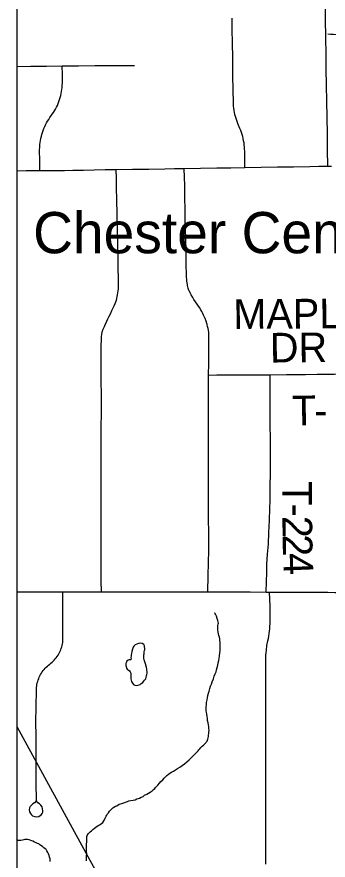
# Model space of a CAD drawing. Extents: x 103424 to 286016, y 38711 to 110967.
# Drawn here: x 103424 to 106590, y 76283 to 84863 of the extents above; entities that cross this region are included whole.
import ezdxf

# ---------------------------------------------------------------- set-up
doc = ezdxf.new("R2010")
doc.units = 0
for name, color, linetype in [('GM_X_Corporation', 7, 'Continuous'), ('GM_X_Minor_Lake', 7, 'Continuous'), ('GM_X_Minor_River', 7, 'Continuous'), ('GM_X_Rail_Line', 7, 'Continuous'), ('GM_X_Township_Road', 7, 'Continuous'), ('GM_X_Township_Road_Text', 7, 'Continuous'), ('GM_X_Unincorporated_Text', 7, 'Continuous'), ('GM_X_US_Route', 7, 'Continuous')]:
    doc.layers.add(name, color=color, linetype=linetype)

msp = doc.modelspace()

# ---------------------------------------------------------------- linework, layer by layer
at = {"layer": 'GM_X_Corporation'}
msp.add_lwpolyline([(103423.7, 96534.8), (103423.7, 38711.2), (175679.7, 38711.2), (175679.7, 110967.2), (119699, 110967.2), (119716.9, 106542.5), (119719.8, 106322.8), (119720.8, 106006.3), (119709.7, 99445.7), (119706.4, 99064.2), (119663.9, 96690), (117026.4, 96688.2), (115542.1, 96665), (105081.7, 96574.5)], close=True, dxfattribs=at)
msp.add_lwpolyline([(103423.7, 96534.8), (103423.7, 70904.9), (107977, 70917.3), (117928.9, 70934.4), (117946.9, 70934.9), (119688.2, 70990.2), (119635, 74016.7), (119631.7, 75117.1), (119628.6, 75451.2), (119621.3, 75805.1), (119622.8, 76073.8), (119627.2, 76341.1), (119628.6, 76885.8), (119631.6, 77245.6), (119644.2, 78899.8), (119644.5, 79431.3), (119642.9, 80216.4), (119641.6, 80653.5), (119641.6, 81200.9), (119640.3, 81697.7), (119639, 82590.1), (119639, 83128.3), (119639, 84504.6), (119641.6, 85722.3)], dxfattribs=at)
at = {"layer": 'GM_X_Minor_Lake'}
for points in [[(104660.3, 78487.2), (104626.1, 78474.7), (104612.2, 78458.4), (104606.2, 78448.3), (104600.4, 78430), (104594.6, 78405.7), (104588.8, 78383.4), (104586.9, 78371.3), (104585.1, 78357.2), (104583.2, 78345), (104587.4, 78330.9), (104581.5, 78320.8), (104567.3, 78320.6), (104557.3, 78318.5), (104543.3, 78306.2), (104539.3, 78296.1), (104533.4, 78281.9), (104533.6, 78271.8), (104531.7, 78261.7), (104533.8, 78251.6), (104538, 78237.5), (104544.2, 78225.5), (104556.4, 78217.5), (104568.6, 78209.5), (104576.8, 78199.5), (104583, 78185.4), (104583.2, 78175.3), (104581.4, 78155.1), (104581.5, 78143), (104583.7, 78128.9), (104585.9, 78112.7), (104590.1, 78100.7), (104598.4, 78082.6), (104612.7, 78066.6), (104624.8, 78062.6), (104639, 78060.8), (104655.1, 78062.9), (104667.2, 78067.1), (104677.3, 78071.2), (104689.3, 78079.4), (104703.3, 78091.7), (104713.3, 78099.9), (104723.2, 78112.1), (104735.2, 78128.4), (104739.1, 78140.5), (104742.9, 78160.8), (104746.8, 78170.9), (104748.7, 78185.1), (104748.5, 78199.2), (104746.3, 78217.4), (104744.1, 78227.4), (104741.9, 78243.6), (104731.4, 78279.8), (104729.3, 78289.9), (104718.7, 78320.9)], [(104718.7, 78320.9), (104716.6, 78334.2), (104714.5, 78346.3), (104714.4, 78356.4), (104716.2, 78370.6), (104718.1, 78382.7), (104718, 78392.8), (104719.9, 78402.9), (104721.7, 78415.1), (104725.6, 78427.2), (104725.5, 78437.3), (104723.3, 78451.5), (104721.2, 78461.5), (104715, 78475.6), (104698.7, 78485.6), (104684.5, 78489.4), (104668.4, 78487.3), (104660.3, 78487.2)]]:
    msp.add_lwpolyline(points, dxfattribs=at)
at = {"layer": 'GM_X_Minor_River'}
for points in [[(105058.9, 77214.6), (105082.9, 77228.9), (105105, 77245.3), (105129, 77263.7), (105153, 77282.2), (105175, 77304.6), (105194.9, 77325), (105214.9, 77341.4), (105230.9, 77357.7), (105246.9, 77374), (105256.8, 77384.2), (105266.8, 77394.4), (105274.8, 77404.6), (105284.8, 77414.8), (105294.7, 77427), (105308.7, 77441.3), (105320.7, 77453.5), (105332.7, 77461.7), (105358.6, 77492.3), (105362.5, 77504.4), (105366.4, 77514.6), (105370.3, 77526.7), (105372.2, 77540.9), (105374, 77557.1), (105375.9, 77571.2), (105377.7, 77583.3), (105379.5, 77601.6), (105377.3, 77621.7), (105375.1, 77637.9), (105372.8, 77658), (105368.6, 77678.2), (105364.2, 77702.4), (105361.9, 77724.6), (105357.7, 77744.7), (105355.4, 77766.9), (105351.1, 77787.1), (105348.9, 77803.2), (105348.7, 77819.4), (105348.5, 77841.6), (105352.3, 77863.9), (105354, 77886.1), (105357.7, 77912.4), (105361.5, 77934.7), (105365.3, 77956.9), (105371.1, 77981.2), (105378.9, 78003.5), (105384.7, 78027.8), (105392.5, 78052.1), (105402.3, 78072.4), (105410.1, 78096.7), (105423.9, 78127.2), (105431.7, 78153.5), (105441.5, 78177.9), (105449.3, 78200.2), (105455.2, 78220.4), (105461, 78242.7), (105466.7, 78267), (105472.5, 78289.3), (105476.3, 78313.5), (105480.1, 78335.8), (105483.8, 78360.1), (105487.5, 78390.4), (105491.3, 78414.7), (105491, 78436.9), (105492.8, 78459.1), (105492.5, 78483.4), (105487.9, 78533.8), (105483.6, 78550), (105479.4, 78568.1), (105475.2, 78584.2), (105470.9, 78602.3), (105468.6, 78628.6), (105468.3, 78650.8), (105468.1, 78669), (105470, 78683.1), (105473.9, 78695.3), (105471.7, 78707.4), (105467.5, 78721.5), (105461.2, 78739.6), (105454.9, 78765.8), (105444.6, 78783.9), (105436.4, 78793.9), (105434.3, 78795.9)], [(104132.6, 76276.1), (104132, 76330.7), (104133.8, 76348.8), (104133.6, 76367), (104131.3, 76387.2), (104133.1, 76405.4), (104132.9, 76423.6), (104132.7, 76445.8), (104134.4, 76470), (104134.1, 76494.3), (104135.9, 76510.5), (104135.8, 76522.6), (104139.7, 76532.7), (104149.6, 76549), (104167.6, 76569.4), (104181.6, 76581.6), (104197.6, 76595.9), (104211.6, 76608.2), (104225.6, 76616.4), (104239.6, 76626.6), (104255.7, 76636.9), (104269.7, 76645.1), (104283.7, 76655.4), (104297.7, 76665.6), (104307.6, 76683.9), (104313.6, 76694), (104321.5, 76710.3), (104331.3, 76730.6), (104337.3, 76740.7), (104345.2, 76755), (104355.2, 76763.1), (104365.1, 76781.4), (104375.1, 76791.6), (104385, 76801.8), (104399, 76814.1), (104411, 76822.3), (104427.1, 76832.5), (104439.2, 76836.7), (104465.2, 76851.1), (104479.3, 76855.3), (104491.4, 76859.4), (104501.5, 76863.6), (104549.7, 76880.2), (104563.8, 76884.4), (104584, 76888.6), (104606.1, 76892.9), (104626.3, 76897.1), (104644.4, 76905.4), (104670.5, 76913.7), (104688.6, 76922), (104706.7, 76930.3), (104722.7, 76942.5), (104744.8, 76954.9), (104762.9, 76963.1), (104780.9, 76973.4), (104798.9, 76987.7), (104814.9, 77002), (104826.9, 77012.3), (104834.9, 77022.4), (104846.8, 77036.7), (104856.8, 77046.9), (104874.7, 77067.3), (104888.7, 77083.6), (104906.7, 77099.9), (104922.6, 77118.3), (104936.6, 77130.5), (104950.6, 77144.8), (104964.6, 77157), (104980.6, 77167.3), (104996.7, 77177.6), (105016.7, 77187.9), (105036.8, 77200.2), (105058.9, 77214.6)], [(103763.1, 76270.4), (103760.8, 76294.6), (103756.5, 76312.8), (103752.3, 76330.9), (103746, 76347), (103737.8, 76361.1), (103729.5, 76377.1), (103721.3, 76389.2), (103711.1, 76397.1), (103696.8, 76409.1), (103684.6, 76421.1), (103666.2, 76433.1), (103656.1, 76439), (103645.9, 76447), (103633.7, 76452.9), (103619.5, 76458.8), (103603.2, 76466.8), (103585, 76474.7), (103564.7, 76482.5), (103548.5, 76488.4), (103532.3, 76492.3), (103518.1, 76494.2), (103504, 76494.1), (103493.9, 76489.9), (103479.8, 76485.7), (103465.7, 76483.6), (103455.6, 76481.4), (103439.5, 76481.3), (103427.3, 76483.2), (103423.7, 76489.5)]]:
    msp.add_lwpolyline(points, dxfattribs=at)
at = {"layer": 'GM_X_Rail_Line'}
msp.add_lwpolyline([(103423.7, 77642.6), (104166, 76280.9), (107163.5, 70870.4), (107374.6, 70584.2), (107548.1, 70377.7), (107675.1, 70305.5), (107983.3, 70249.1), (108679.2, 69977.3), (109351.9, 69695.5), (110309.6, 69221.5), (110614.5, 69082.2), (110922.7, 69062.3), (111038.6, 69148.5), (111217.6, 69480), (111333.6, 69665.7), (111519.1, 69795), (111678.2, 69838), (112046, 69785), (112529.9, 69702.1), (112964, 69695.5)], dxfattribs=at)
at = {"layer": 'GM_X_Township_Road'}
for points in [[(106566, 84636.9), (106565.5, 84663.5), (106562.9, 84828.5), (106561.2, 84927.4), (106559.6, 85026.3), (106558.1, 85043.8), (106555.1, 85061.2), (106551.1, 85078.3), (106544.3, 85099.2), (106535.7, 85119.4), (106527.7, 85135), (106518.6, 85150), (106508.3, 85164.3), (106497.3, 85177.9), (106424.8, 85261.5)], [(105743.7, 83329.7), (105742.5, 83412.3), (105741.3, 83494.9), (105740.6, 83516.5), (105739.3, 83538.1), (105737, 83559.6), (105734, 83581.1), (105730.3, 83602.5), (105725.7, 83623.6), (105720.7, 83644.6), (105714.7, 83665.4), (105708.1, 83686), (105700.8, 83706.4), (105692.8, 83726.4), (105675.2, 83766), (105667.2, 83786.1), (105659.9, 83806.5), (105653.1, 83827), (105647.3, 83847.8), (105642, 83868.8), (105637.5, 83890), (105634, 83911.3), (105631, 83932.8), (105628.7, 83954.3), (105627.2, 83975.9), (105626.5, 83997.5), (105624.5, 84109.9), (105621.8, 84274.9), (105619.2, 84439.9), (105616.5, 84605), (105614.6, 84727.5), (105612.6, 84850)], [(106586.2, 84688.6), (106615.2, 84687), (106642.8, 84685.4), (106725, 84684.6), (106890, 84685.9), (107008.4, 84686.8), (107126.8, 84687.8), (107291.8, 84690.6), (107456.8, 84693.3), (107563.3, 84695.1), (107669.8, 84696.9), (107834.8, 84699), (107937.2, 84700.2), (108039.7, 84701.5), (108158.9, 84700.6), (108278.1, 84699.8)], [(106587, 83343.2), (106584.4, 83508.2), (106581.7, 83673.3), (106579, 83838.3), (106576.3, 84003.3), (106573.6, 84168.4), (106570.9, 84333.4), (106568.2, 84498.4), (106566, 84636.9)], [(103423.7, 84359), (103561.7, 84360.3), (103723.8, 84361.9), (103885.9, 84363.4), (104051, 84364.7), (104216.1, 84366), (104381.1, 84367.3), (104500.7, 84368.3), (104620.2, 84369.3)], [(103657.4, 83298.7), (103656.4, 83400.1), (103655.5, 83501.5), (103656.7, 83543.5), (103658.5, 83564.4), (103660.8, 83585.3), (103664.1, 83606), (103668.1, 83626.6), (103672.9, 83647), (103678.2, 83667.2), (103684.5, 83687.3), (103691.3, 83707.1), (103698.9, 83726.7), (103707.4, 83745.9), (103716.3, 83764.9), (103726.1, 83783.4), (103736.4, 83801.6), (103747.5, 83819.5), (103759.1, 83837), (103783.8, 83870.9), (103795.3, 83888.3), (103806.4, 83906.1), (103816.8, 83924.4), (103826.6, 83943), (103835.7, 83961.9), (103844, 83981.2), (103851.5, 84000.7), (103858.6, 84020.5), (103864.6, 84040.5), (103870.2, 84060.8), (103874.7, 84081.3), (103878.8, 84101.8), (103882.1, 84122.5), (103884.6, 84143.3), (103886.1, 84164.3), (103886.8, 84186.8), (103886.4, 84275.1), (103885.9, 84363.4)], [(104434.8, 83309), (104599.8, 83311.6), (104764.9, 83314.1), (104929.9, 83316.7), (105028.3, 83318.2), (105126.7, 83319.7), (105291.7, 83322.4), (105456.7, 83325.1), (105600.3, 83327.4), (105743.7, 83329.7), (105908.8, 83332.4), (106073.8, 83335), (106238.8, 83337.7), (106403.9, 83340.3), (106495.5, 83341.8), (106587, 83343.2), (106625.5, 83343.8)], [(105367.5, 79012.1), (105370.5, 79177.2), (105372.8, 79306.8), (105375.1, 79436.4), (105374.7, 79601.5), (105374.3, 79766.5), (105373.8, 79931.6), (105373.4, 80096.7), (105373, 80225.5), (105372.7, 80354.2), (105373.9, 81217.4), (105374.8, 81340.2), (105375.7, 81463.1), (105376.3, 81603.3), (105375, 81653.3), (105368.6, 81692.3), (105364.1, 81710.8), (105359.1, 81731.9), (105355.5, 81743.9), (105348, 81765.4), (105338.1, 81793.5), (105331.3, 81806.9), (105322.7, 81828.8), (105315.2, 81843.8), (105303.9, 81865.5), (105294.6, 81881.1), (105280.3, 81905.8), (105240.7, 81964), (105225, 81987.6), (105213.3, 82006.2), (105197, 82034.2), (105186.5, 82055.1), (105179.1, 82070.7), (105173.6, 82079.1), (105166.6, 82102.6), (105160.3, 82128.9), (105157.6, 82139.6), (105155.3, 82154.9), (105152.6, 82171.7), (105151, 82188.3), (105150.1, 82219.7), (105147, 82363.3), (105144.7, 82481.3), (105142.4, 82599.3), (105139.5, 82705.6), (105136.7, 82811.8), (105134.9, 82912.6), (105133.1, 83013.3), (105130.6, 83147.4), (105128.6, 83228.3), (105126.7, 83319.7)], [(103423.7, 83297.2), (103428.1, 83297.3), (103518.8, 83297.8), (103657.4, 83298.7), (103822.5, 83300.2), (103907.7, 83301), (103993, 83301.8), (104101.7, 83304.3), (104210.5, 83306.9), (104322.7, 83308), (104434.8, 83309)], [(104282.9, 79012.5), (104281.8, 79123.6), (104281.1, 79270.7), (104280.4, 79417.8), (104280.8, 80349.4), (104281.7, 80514.4), (104282.6, 80677.3), (104283.5, 80840.1), (104282.8, 81005.2), (104282, 81170.2), (104281.2, 81335.3), (104280.8, 81419.2), (104280.4, 81503.2), (104283.5, 81592), (104285.1, 81612.4), (104287.3, 81628.1), (104291.7, 81656.5), (104300.1, 81683.5), (104313.8, 81713.4), (104321.6, 81730.6), (104337.6, 81765), (104349.9, 81789.3), (104359.8, 81809), (104377.9, 81846.8), (104390.6, 81873.3), (104403, 81900.6), (104412.9, 81921.7), (104423, 81945.5), (104429.2, 81962.1), (104435.6, 81981.7), (104440.1, 81997.7), (104445.4, 82017), (104448.8, 82036), (104452.2, 82054.8), (104455, 82073.6), (104456.7, 82090.7), (104458, 82112.5), (104458.6, 82129.3), (104456.7, 82205.1), (104454.6, 82302.4), (104452.5, 82399.7), (104450, 82540.4), (104447.4, 82681.2), (104443.9, 82846.2), (104440.3, 83011.3), (104438.1, 83114.5), (104435.9, 83217.7), (104434.8, 83309)], [(105373.9, 81217.4), (105459.2, 81219.6), (105624.3, 81220.1), (105846.2, 81220.8), (105999.7, 81221.3), (106164.7, 81223.1), (106262.9, 81224.2), (106361, 81225.2), (106479.2, 81226.5), (106597.4, 81227.8), (106650.8, 81227.5), (106783.9, 81229.2), (106916.9, 81230.9), (107018.7, 81232.2), (107120.5, 81233.5)], [(105958.7, 79010.8), (105961.4, 79117.1), (105964.6, 79204.9), (105967.7, 79292.6), (105974.5, 79394.4), (105981.4, 79496.1), (105987.8, 79616.8), (105992.5, 79737.9), (105997.2, 79858.9), (105998.7, 79943.3), (105999.5, 80093), (106002.5, 80213), (106001, 81067.3), (105999.7, 81221.3)], [(103619.6, 76886), (103603.9, 76866.5), (103587.5, 76856.8), (103571, 76841.9), (103559.8, 76829.9), (103553.8, 76813.4), (103549.3, 76793.2), (103552.3, 76775.3), (103561.3, 76758.1), (103571.7, 76743.9), (103583, 76734.9), (103606.1, 76726), (103622.6, 76723.7), (103647.3, 76728.2), (103661.5, 76737.9), (103673.5, 76747.6), (103682.4, 76758.1), (103687.6, 76770.1), (103689.2, 76784.3), (103682.4, 76824.7), (103669, 76841.1), (103653.2, 76856.1), (103636, 76865), (103626.3, 76880.7), (103622.6, 76897.2), (103621.9, 76935.3), (103620.7, 77020.2), (103619.6, 77105.1), (103620.4, 77262.5), (103621.1, 77419.9), (103619.6, 77551.9), (103618.1, 77683.9), (103620.5, 77845.8), (103622.8, 78007.7), (103624.1, 78038.9), (103625.8, 78054.4), (103628.4, 78069.8), (103631.7, 78085), (103635.7, 78100.1), (103640.2, 78115), (103645.5, 78129.6), (103651.6, 78144), (103658.4, 78158.1), (103665.7, 78171.9), (103673.5, 78185.3), (103682, 78198.3), (103691.3, 78210.8), (103701.2, 78223), (103711.5, 78234.7), (103722.3, 78245.9), (103733.7, 78256.5), (103745.5, 78266.6), (103757.8, 78276.1), (103770.2, 78285.7), (103782, 78295.8), (103793.6, 78306.4), (103804.4, 78317.6), (103814.7, 78329.4), (103824.6, 78341.5), (103833.7, 78354.1), (103842.2, 78367.1), (103850.3, 78380.5), (103857.6, 78394.2), (103864.4, 78408.3), (103870.2, 78422.7), (103875.7, 78437.4), (103880.3, 78452.2), (103884.3, 78467.3), (103887.3, 78482.6), (103889.9, 78498), (103891.6, 78513.5), (103892.9, 78529), (103891.8, 79013.7)], [(105955, 76241), (105955.7, 76571.1), (105956.2, 78366.8), (105958, 78391), (105961, 78417.6), (105967.7, 78465.2), (105976.5, 78513.3), (105982, 78537.8), (105986.6, 78562.4), (105990.6, 78587.1), (105993.6, 78612), (105996.2, 78636.9), (105997.9, 78661.9), (105999, 78687), (106000.3, 78776.5), (106001.6, 78866), (105992.2, 79010.5)]]:
    msp.add_lwpolyline(points, dxfattribs=at)
at = {"layer": 'GM_X_US_Route'}
for points in [[(103423.7, 79013.7), (103891.8, 79013.7), (104282.9, 79012.5), (105228, 79012.9), (105367.5, 79012.1), (105399.9, 79012.6), (105795.1, 79012), (105958.7, 79010.8), (105992.2, 79010.5), (106153, 79010.8), (106283.7, 79010.4)], [(106283.7, 79010.4), (106450.9, 79009.8), (106588.1, 79008.3), (106658.9, 79007.3), (106818.6, 79006.6)]]:
    msp.add_lwpolyline(points, dxfattribs=at)

# ---------------------------------------------------------------- texts
at = {"layer": 'GM_X_Township_Road_Text'}
for s, height, rotation, p in [('MAPLE', 301.87, 0.40272, (105625.8, 81686.9)), ('DR', 301.87, 0.49254, (105998, 81345.2)), ('T', 301.9, 0.30428, (106221.5, 80707.1)), ('-', 301.9, 0.33033, (106447.4, 80708.3)), ('T', 301.9, 270.01286, (106124.2, 80137.4)), ('-', 301.9, 270.09721, (106124.3, 79911.1)), ('2', 301.9, 270.44779, (106124.5, 79785.1)), ('2', 301.9, 271.08932, (106126, 79595.5)), ('4', 301.9, 272.28947, (106129.7, 79402.7))]:
    msp.add_text(s, height=height, rotation=rotation, dxfattribs=at).set_placement(p)
at = {"layer": 'GM_X_Unincorporated_Text'}
msp.add_text('Chester Center', height=419.602, rotation=0.00001, dxfattribs=at).set_placement((103588.8, 82457.2))

doc.saveas('drawing.dxf')
